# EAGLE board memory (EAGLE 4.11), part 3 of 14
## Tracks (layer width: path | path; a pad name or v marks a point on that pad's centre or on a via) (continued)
-BT00(B) (continued)
  Route3 0.254: F25.T2 191.77,19.69 187.32,19.69 187.32,20.32 130.18,77.47 130.18,86.99 128.91,88.27 E30.T2
-BT12  (via drill 0.61)
  Top 0.254: v133.35,299.72 132.08,298.45 132.08,295.91 B30.S2
  Route2 0.254: v211.46,365.12 213.36,367.03 222.88,367.03 223.52,366.4 226.06,366.4 227.33,367.67 229.87,367.67 A22.R2
  Route3 0.254: v170.18,292.1 175.26,297.18 175.26,297.81 179.07,297.81 B26.R2 | v167,358.78 163.19,354.97 163.19,342.9 158.75,338.46 158.75,311.79 149.22,302.26 149.22,296.55 v147.96,295.28
  Bottom 0.254: v211.46,365.12 210.82,365.12 209.55,363.86 205.1,363.86 204.47,363.22 201.29,363.22 200.66,363.86 198.12,363.86 197.49,363.22 188.59,363.22 187.96,363.86 183.51,363.86 182.88,364.49 A26.S2 182.25,364.49 180.97,363.22 173.99,363.22 173.35,363.86 172.09,363.86 v167,358.78 | v133.35,299.72 125.09,299.72 124.46,300.36 121.92,300.36 121.28,299.72 112.39,299.72 108.58,303.53 99.69,303.53 99.06,302.9 94.61,302.9 93.98,302.26 B33.P2 | v170.18,292.1 168.91,293.37 161.29,293.37 160.66,294 151.76,294 151.13,293.37 148.59,293.37 147.96,294 | 147.96,294 139.06,294 138.43,293.37 135.89,293.37 134.62,294.64 132.08,294.64 B30.S2 | v147.96,295.28 147.96,294
-BT13  (via drill 0.61)
  Top 0.254: v156.84,361.95 v163.83,368.94
  Route2 0.254: v142.88,362.59 145.41,360.05 149.86,360.05 150.5,360.68 155.57,360.68 v156.84,361.95 | v163.83,368.94 165.1,370.21 172.72,370.21 176.53,374.02 179.07,374.02 A26.N2
  Route3 0.254: v142.88,362.59 142.88,361.31 135.89,354.33 135.89,344.81 133.35,342.27 133.35,328.93 132.08,327.66 B30.E2
-BT(00-01)  (via drill 0.61)
  Top 0.254: v150.5,330.2 155.57,335.28 155.57,342.9 161.93,349.25 161.93,361.31 165.1,364.49 165.1,394.34 181.61,410.85 184.15,410.85 184.15,400.69 179.71,396.24 179.71,394.34 A26.F2
  Route2 0.254: v150.5,330.2 148.59,328.3 145.41,328.3 144.78,327.66 B29.E2
-BT(00-11)  (via drill 0.61)
  Top 0.254: v128.91,344.17 128.91,341 123.83,335.92 123.83,327.66 119.38,327.66 B31.E2 | v150.5,344.17 154.31,347.98 v154.31,353.7
  Route3 0.254: v186.06,357.5 187.32,358.78 187.32,372.11 201.93,386.72 204.47,386.72 A24.J2
  Bottom 0.254: v128.91,344.17 142.88,344.17 144.15,342.9 149.22,342.9 v150.5,344.17 | v154.31,353.7 162.56,353.7 166.37,357.5 175.26,357.5 175.9,356.87 184.78,356.87 185.42,357.5 v186.06,357.5
-C  (via drill 0.61)
  Route2 0.254: v277.5,368.3 260.99,351.79 250.19,351.79 245.11,356.87 237.49,356.87 233.68,360.68 224.79,360.68 220.98,356.87 215.9,356.87 v214,354.97 | v198.75,325.75 200.03,324.49 204.47,324.49 B24.F2
  Route3 0.254: v155.57,290.2 155.57,287.66 154.31,286.39 B28.V2 | B25.V2 191.77,286.39 188.59,286.39 v186.06,288.93 190.5,293.37 190.5,299.09 193.04,301.62 190.5,304.17 190.5,318.14 192.41,320.04 192.41,321.31 190.5,323.22 v190.5,327.66 | B24.K2 207.65,314.96 206.38,316.23 206.38,321.95 205.1,323.22 B24.F2 205.1,324.49 205.1,327.03 206.38,328.3 206.38,347.35 v214,354.97
  Bottom 0.254: v155.57,290.2 162.56,290.2 163.19,290.83 172.09,290.83 172.72,290.2 175.26,290.2 175.9,290.83 184.15,290.83 v186.06,288.93 | v277.5,368.3 278.13,368.3 279.4,367.03 281.94,367.03 285.12,370.21 287.65,370.21 288.29,369.57 290.83,369.57 292.74,371.48 296.55,371.48 A17.P2 | v190.5,327.66 191.13,328.3 196.22,328.3 v198.75,325.75
-CA  (via drill 0.61)
  Top 0.254: v165.1,330.2 165.1,318.14 158.75,311.79 158.75,297.18 157.48,295.91 B28.S2 | v182.25,346.71 182.88,347.35 v182.88,351.16 | A22.D2 229.87,399.42 228.6,398.15 228.6,389.25 229.87,387.99 A22.J2
  Route3 0.254: v165.1,330.2 165.1,339.73 170.81,345.44 v170.81,346.71 | v204.47,351.79 206.38,353.7 206.38,361.31 229.87,384.81 229.87,386.72 A22.J2
  Bottom 0.254: v170.81,346.71 v182.25,346.71 | v182.88,351.16 183.51,351.79 v204.47,351.79
-CAC  (via drill 0.61)
  Top 0.254: 463.55,74.93 463.55,94.61 460.38,97.79 460.38,102.23 461.64,103.5 461.64,104.14 E04.M2 | 463.55,74.93 463.55,36.83 462.28,35.56 F04.M2 | v320.68,78.1 320.68,49.53 321.94,48.26 F15.H2 | 463.55,74.93 v461.64,74.93 | A19.M2 271.14,378.46 270.51,379.1 270.51,382.91 269.88,383.54 269.88,388.62 268.61,389.89 268.61,393.06 A19.F2 | v271.14,393.7 278.13,400.69 278.13,401.32 282.57,405.77 282.57,410.21 287.65,415.29 v298.45,415.29 | v316.23,414.02 318.77,416.56 318.77,418.47 407.67,418.47 407.67,417.2 v414.65,410.21
  Route2 0.254: v271.14,393.7 268.61,393.7 A19.F2 | v298.45,415.29 299.72,414.02 v316.23,414.02 | v414.65,410.21 445.77,379.1 454.66,379.1 455.3,379.73 460.38,379.73 461.64,378.46 A04.M2 | v462.92,219.71 462.92,220.98 466.73,224.79 466.73,240.66 462.28,240.66 C04.M2
  Route3 0.254: E04.M2 462.28,105.41 463.55,106.68 463.55,169.54 462.28,170.81 D04.M2 462.28,172.09 463.55,173.35 463.55,193.04 462.28,194.31 462.28,194.94 463.55,196.22 463.55,216.53 462.28,217.81 462.28,219.07 v462.92,219.71 | v449.58,304.17 450.85,302.9 450.85,290.2 457.2,283.85 457.2,250.82 455.93,249.56 460.38,245.11 460.38,243.2 461.64,241.94 C04.M2 | A04.M2 462.28,377.19 463.55,375.92 463.55,309.88 462.28,308.61 B04.M2
  Bottom 0.254: v320.68,78.1 349.25,78.1 350.52,76.83 353.06,76.83 353.69,77.47 366.39,77.47 368.3,79.38 403.86,79.38 406.4,76.83 412.12,76.83 412.75,76.2 430.53,76.2 431.8,74.93 v461.64,74.93 | v449.58,304.17 452.12,306.71 454.66,306.71 455.3,306.07 460.38,306.07 461.64,307.34 B04.M2
-CL  (via drill 0.61)
  Top 0.254: v319.4,65.41 319.4,72.39 315.6,76.2 v315.6,81.91 | v208.91,131.44 208.28,132.08 v208.28,134.62 | v165.1,253.36 165.1,286.39 v167,288.29
  Route2 0.254: v464.82,69.22 462.92,71.12 421.64,71.12 419.74,69.22 398.14,69.22 396.88,67.94 393.06,67.94 392.43,68.58 345.44,68.58 338.45,61.59 337.19,61.59 336.55,62.23 330.2,62.23 327.02,65.41 v319.4,65.41 | v315.6,81.91 313.06,84.45 304.17,84.45 300.36,80.64 286.38,80.64 264.8,102.23 263.52,102.23 256.54,109.22 250.19,109.22 243.84,115.57 237.49,115.57 236.85,116.2 227.97,116.2 227.33,115.57 226.69,115.57 214.63,127.63 212.72,127.63 v208.91,131.44 | v208.28,134.62 207.65,135.25 205.1,135.25 201.29,139.06 192.41,139.06 179.07,152.4 179.07,154.31 178.44,154.31 169.54,163.19 163.19,163.19 v157.48,168.91
  Route3 0.254: v157.48,168.91 155.57,170.81 155.57,190.5 154.31,191.77 155.57,193.04 155.57,203.2 154.31,204.47 154.31,217.17 155.57,218.44 155.57,243.84 v165.1,253.36
  Bottom 0.254: v464.82,69.22 476.25,69.22 476.25,53.34 475.62,52.7 473.07,52.7 471.81,51.44 F03.F2 | v167,288.29 169.54,288.29 B27.U2
-CLK  (via drill 0.61)
  Top 0.254: B09.K2 398.14,314.96 398.14,318.77 396.88,320.04 396.88,328.3 395.61,329.56 B09.D2 | v59.05,349.89 59.05,351.16 47.62,362.59 47.62,372.75 41.91,372.75 41.27,372.11 41.27,367.03 42.55,365.76 A37.S2 | v95.89,346.71 107.95,346.71 v107.95,329.56
  Route2 0.254: v107.95,329.56 109.22,328.3 109.86,328.3 110.49,328.93 113.03,328.93 113.67,328.3 122.56,328.3 123.19,328.93 130.81,328.93 137.16,335.28 144.78,335.28 148.59,331.47 156.84,331.47 160.02,328.3 160.66,328.3 164.47,332.11 173.35,332.11 173.99,331.47 176.53,331.47 177.16,332.11 186.06,332.11 186.69,331.47 189.23,331.47 189.87,332.11 198.75,332.11 199.39,331.47 201.93,331.47 202.56,332.11 211.46,332.11 212.09,331.47 214.63,331.47 215.26,332.11 224.16,332.11 224.79,331.47 227.33,331.47 227.97,332.11 236.85,332.11 237.49,331.47 246.38,331.47 250.19,335.28 259.08,335.28 262.89,331.47 265.43,331.47 266.06,332.11 274.95,332.11 275.59,331.47 278.13,331.47 278.76,332.11 287.65,332.11 288.29,331.47 290.83,331.47 291.46,332.11 300.36,332.11 300.99,331.47 303.53,331.47 304.17,332.11 313.06,332.11 313.69,331.47 322.58,331.47 326.39,335.28 335.28,335.28 339.09,331.47 347.98,331.47 351.79,335.28 360.68,335.28 364.49,331.47 367.03,331.47 367.67,332.11 376.56,332.11 377.19,331.47 379.73,331.47 380.37,332.11 389.25,332.11 390.52,330.84 394.97,330.84 B09.D2
  Route3 0.254: v107.95,329.56 107.95,316.87 111.12,313.69 111.12,299.09 115.57,299.09 B31.R2
  Bottom 0.254: v107.95,329.56 103.5,329.56 B32.D2 | v59.05,349.89 60.96,347.98 81.28,347.98 81.92,347.35 85.09,347.35 85.72,346.71 v95.89,346.71
-CLL  (via drill 0.61)
  Top 0.254: v282.57,53.34 v282.57,30.48 | v302.89,57.15 304.8,59.05 304.8,75.56 v306.07,76.83 | v177.8,277.5 177.8,307.34 180.97,310.52 180.97,318.77 182.25,320.04 B26.H2 | v252.73,81.91 252.09,81.28 252.09,69.22 250.82,67.94 250.82,39.37 v261.62,28.58
  Route2 0.254: v322.58,83.82 324.49,85.72 v325.12,85.72 | v382.27,153.03 374.01,144.78 365.76,144.78 v347.98,127
  Route3 0.254: v309.25,76.83 309.88,77.47 v309.88,82.55 | v407.67,248.92 406.4,247.65 406.4,232.41 403.23,229.23 403.23,201.29 406.4,198.12 406.4,189.23 405.13,187.96 405.13,186.69 403.23,184.78 403.23,177.8 401.95,176.53 403.23,175.26 403.23,170.81 403.86,170.18 403.86,166.37 403.23,165.73 403.23,160.66 v401.32,158.75 | v347.98,127 346.07,125.09 346.07,116.84 345.44,116.2 345.44,115.57 346.07,114.93 346.07,113.03 344.81,111.76 344.81,109.85 346.07,108.58 346.07,93.98 347.35,92.71 E13.S2 | v198.12,276.23 196.85,274.96 196.85,154.31 200.66,150.5 200.66,144.78 v201.29,144.14 | v210.82,144.14 215.9,139.06 215.9,132.08 219.07,128.91 219.07,107.31 219.71,106.68 219.71,106.04 219.07,105.41 219.07,97.16 v220.98,95.25
  Bottom 0.254: v282.57,30.48 277.5,30.48 276.86,29.84 272.42,29.84 271.78,29.21 F19.P2 271.14,29.21 269.88,30.48 263.52,30.48 v261.62,28.58 | v282.57,53.34 282.57,55.25 289.56,55.25 290.19,55.88 299.08,55.88 299.72,55.25 300.99,55.25 v302.89,57.15 | v309.25,76.83 v306.07,76.83 | v309.88,82.55 311.79,84.45 314.96,84.45 315.6,83.82 v322.58,83.82 | v325.12,85.72 327.02,87.63 334.64,87.63 335.28,86.99 338.45,86.99 342.9,91.44 347.35,91.44 E13.S2 | v407.67,248.92 410.85,248.92 410.85,253.36 C08.H2 | v401.32,158.75 399.42,156.84 392.43,156.84 389.25,153.67 382.9,153.67 v382.27,153.03 | v177.8,277.5 178.44,276.86 194.94,276.86 195.58,277.5 196.85,277.5 v198.12,276.23 | v210.82,144.14 v201.29,144.14 | v220.98,95.25 224.16,92.07 224.79,92.07 226.69,90.17 235.59,90.17 236.22,90.8 238.76,90.8 245.11,84.45 250.19,84.45 v252.73,81.91
-CLR  (via drill 0.61)
  Top 0.254: v117.47,123.19 118.75,121.92 118.75,118.11 E31.H2
  Route2 0.254: v115.57,198.12 113.03,200.66 111.12,200.66 111.12,215.26 51.44,274.96 46.35,274.96 20.95,300.36 12.7,300.36 12.7,332.11 37.47,356.87 41.27,356.87 42.55,358.14 A37.U2
  Route3 0.254: v115.57,198.12 114.3,196.85 114.3,160.02 120.65,153.67 120.65,142.24 117.47,139.06 117.47,132.72 116.2,131.44 116.2,128.91 117.47,127.63 v117.47,123.19
-CM  (via drill 0.61)
  Top 0.254: v208.91,84.45 209.55,85.09 v209.55,112.39
  Bottom 0.254: v208.91,84.45 206.38,84.45 205.1,83.18 E24.V2 | v209.55,112.39 209.55,116.84 208.28,116.84 E24.H2
-CMA
  Top 0.254: F14.M2 334.64,35.56 334.64,40.64 F14.K2
-CMB  (via drill 0.61)
  Top 0.254: v429.26,48.9 429.26,50.16 433.07,50.16 F06.F2 | v182.25,208.91 182.88,208.28 v182.88,205.1 | v292.1,208.28 v292.1,181.61 | v309.25,182.25 311.15,180.34 311.15,173.35 309.88,172.09 D16.M2
  Route2 0.254: v398.14,126.36 396.24,128.27 391.16,128.27 384.18,135.25 384.18,155.57 385.44,156.84 385.44,157.48 384.81,157.48 373.38,168.91 373.38,170.81 D11.M2 | v219.71,206.38 220.98,207.64 229.24,207.64 229.87,207.01 233.68,207.01 v234.95,208.28
  Route3 0.254: v411.48,50.16 406.4,55.25 406.4,88.27 403.23,91.44 403.23,104.14 400.05,107.31 400.05,124.46 v398.14,126.36 | v46.35,255.27 47.62,254 47.62,214 v48.9,212.72
  Bottom 0.254: D11.M2 372.75,172.09 368.94,172.09 367.67,173.35 366.39,173.35 365.12,172.09 360.68,172.09 D12.M2 360.05,171.45 356.24,171.45 354.33,169.54 351.79,169.54 350.52,170.81 347.98,170.81 D13.M2 347.35,170.81 346.07,169.54 340.36,169.54 339.09,170.81 335.28,170.81 D14.M2 334.64,170.81 333.38,169.54 327.66,169.54 326.39,170.81 322.58,170.81 D15.M2 321.94,172.09 318.13,172.09 316.87,173.35 315.6,173.35 314.96,172.72 310.51,172.72 309.88,172.09 D16.M2 | v429.26,48.9 418.46,48.9 417.83,49.53 415.29,49.53 414.65,48.9 412.75,48.9 v411.48,50.16 | v46.35,255.27 41.27,255.27 40.01,256.54 C37.F2 | v48.9,212.72 49.53,212.09 75.56,212.09 76.2,212.72 97.16,212.72 97.79,212.09 130.18,212.09 130.81,211.45 132.08,211.45 133.35,212.72 145.41,212.72 149.22,208.91 179.07,208.91 179.71,209.55 181.61,209.55 v182.25,208.91 | v182.88,205.1 183.51,205.74 187.96,205.74 189.23,207.01 211.46,207.01 212.72,205.74 219.07,205.74 v219.71,206.38 | v234.95,208.28 235.59,208.91 241.3,208.91 242.57,210.19 262.89,210.19 264.8,208.28 v292.1,208.28 | v292.1,181.61 293.37,182.88 302.26,182.88 302.89,182.25 v309.25,182.25
-CML  (via drill 0.61)
  Top 0.254: v258.44,375.92 260.35,374.02 v260.35,320.68 | v266.7,281.94 v266.7,317.5 | v299.72,281.94 300.36,281.31 300.36,271.78 301.62,270.51 v301.62,80.64 | F13.E2 347.35,54.61 346.07,55.88 346.07,80.64 344.81,81.91 E13.V2
  Bottom 0.254: v258.44,375.92 252.09,375.92 248.92,379.1 244.47,379.1 243.21,380.37 A21.L2 | v260.35,320.68 261.62,319.41 264.16,319.41 266.06,317.5 v266.7,317.5 | v266.7,281.94 267.33,281.31 290.19,281.31 290.83,281.94 v299.72,281.94 | v301.62,80.64 311.15,80.64 311.79,80.01 342.26,80.01 344.17,81.91 E13.V2
-CONS  (via drill 0.61)
  Top 0.254: v501.65,271.78 v501.65,255.91
  Route2 0.254: v46.35,309.25 57.15,320.04 57.15,331.47 57.78,331.47 71.75,345.44 90.17,345.44 98.42,353.7 149.86,353.7 v161.93,365.76 | v300.36,385.45 302.89,387.99 304.8,387.99 305.44,388.62 308.61,388.62 309.25,389.25 313.06,389.25 316.87,385.45 327.66,385.45 331.47,389.25 340.36,389.25 341,388.62 349.88,388.62 353.69,392.43 361.31,392.43 368.3,385.45 378.46,385.45 382.27,389.25 389.89,389.25 396.24,382.91 403.23,382.91 409.57,376.56 416.56,376.56 420.37,372.75 429.26,372.75 429.89,373.38 431.8,373.38 445.13,360.05 454.66,360.05 455.3,360.68 464.19,360.68 470.54,354.33 476.88,354.33 477.52,353.7 492.76,353.7 497.2,358.14 499.75,358.14 A01.U2 | v429.89,82.55 479.43,132.08 479.43,156.84 481.33,156.84 498.48,173.99 498.48,189.23 v497.2,189.23
  Route3 0.254: v46.35,309.25 46.35,307.98 44.45,306.07 44.45,230.5 43.18,229.23 C37.S2 | v161.93,365.76 165.1,368.94 165.1,375.29 179.07,389.25 v181.61,389.25 | v209.55,389.89 224.79,405.13 235.59,405.13 242.57,398.15 250.82,398.15 250.82,396.24 255.27,391.8 264.16,391.8 264.8,392.43 273.69,392.43 277.5,388.62 286.38,388.62 286.38,389.89 288.93,392.43 291.46,392.43 298.45,385.45 v300.36,385.45 | v429.89,82.55 429.89,74.29 425.45,69.85 425.45,55.88 424.18,54.61 F07.E2 | v500.38,215.9 501.65,217.17 v501.65,255.91
  Bottom 0.254: v181.61,389.25 186.06,389.25 188.59,386.72 189.23,386.72 191.77,389.25 200.66,389.25 201.29,388.62 208.28,388.62 v209.55,389.89 | v497.2,189.23 497.2,192.41 497.84,192.41 501.65,196.22 501.65,215.9 v500.38,215.9 | v501.65,271.78 501.65,277.5 498.48,280.67 498.48,309.25 501.65,312.42 501.65,322.58 500.38,322.58 479.43,343.54 479.43,344.81 490.22,344.81 499.75,354.33 499.75,358.14 A01.U2
-CP  (via drill 0.61)
  Top 0.254: v170.18,269.88 171.45,271.15 171.45,286.39 v173.35,288.29
  Route2 0.254: v46.35,254 44.45,254 44.45,226.06 43.18,224.79 40.01,224.79 C37.T2 | v137.79,250.82 147.32,260.35 148.59,260.35 150.5,258.44 151.76,258.44 154.94,261.62 161.93,261.62 v170.18,269.88 | v173.35,288.29 179.07,294 185.42,294 188.59,297.18 197.49,297.18 198.12,296.55 199.39,296.55 203.2,300.36 210.19,300.36 211.46,301.62 212.09,301.62 214,299.72 222.88,299.72 226.69,303.53 231.78,303.53 232.41,304.17 234.95,304.17 236.22,302.9 238.76,302.9 239.4,303.53 240.03,303.53 241.3,302.26 245.75,302.26 B21.P2
  Bottom 0.254: v46.35,254 48.26,252.09 57.78,252.09 58.42,252.73 60.96,252.73 64.77,248.92 72.39,248.92 76.2,252.73 86.36,252.73 90.17,248.92 99.06,248.92 102.87,252.73 111.76,252.73 112.39,252.09 121.28,252.09 121.92,252.73 124.46,252.73 125.09,252.09 133.99,252.09 134.62,252.73 135.89,252.73 v137.79,250.82
-DC  (via drill 0.61)
  Top 0.254: v226.69,348.62 223.52,345.44 v223.52,339.73
  Route2 0.254: v226.69,348.62 227.97,349.89 271.78,349.89 281.94,360.05 287.65,360.05 294,366.4 300.36,366.4 300.99,367.03 307.34,367.03 310.51,370.21 313.06,370.21 313.69,369.57 316.23,369.57 316.87,370.21 325.75,370.21 326.39,369.57 330.83,369.57 331.47,368.94 A14.R2 | v223.52,339.73 222.25,338.46 217.81,338.46 214.63,341.63 173.99,341.63 167.64,335.28 161.29,335.28 160.66,334.65 151.76,334.65 147.96,338.46 139.06,338.46 132.08,331.47 123.19,331.47 119.38,335.28 110.49,335.28 104.14,328.93 97.79,328.93 97.16,328.3 88.27,328.3 84.45,332.11 75.56,332.11 68.58,325.12 61.59,325.12 60.33,326.39 v60.33,327.03
  Route3 0.254: v62.23,297.18 60.33,299.09 v60.33,327.03
  Bottom 0.254: v62.23,297.18 66.67,297.18 67.94,295.91 B35.S2 | v60.33,327.03 55.88,327.03 B36.E2
-DCA  (via drill 0.61)
  Top 0.254: 257.18,162.56 257.18,289.56 259.08,291.47 259.08,294.64 B20.S2 | 257.18,162.56 257.18,36.83 258.44,35.56 F20.M2 | v252.09,306.07 254,304.17 v254,296.55 | 257.18,162.56 v259.08,162.56
  Route2 0.254: v259.08,162.56 263.52,167 271.78,167 275.59,163.19 278.13,163.19 278.76,163.83 287.65,163.83 288.29,163.19 292.74,163.19 293.37,162.56 D17.R2
  Bottom 0.254: v252.09,306.07 251.46,306.71 247.01,306.71 246.38,307.34 B21.M2 | v254,296.55 255.27,295.28 258.44,295.28 B20.S2
-DEPS  (via drill 0.61)
  Top 0.254: v490.86,327.66 492.12,328.93 492.12,338.46 v490.86,339.73 | v379.73,349.25 374.65,354.33 374.65,359.41 v372.75,361.31 | v205.74,276.23 207.65,278.13 207.65,288.29 B24.U2 | v267.97,347.35 261.62,341 v261.62,339.73
  Route2 0.254: v490.86,339.73 485.77,344.81 479.43,344.81 476.88,347.35 447.04,347.35 v445.13,349.25 | v34.29,295.28 39.37,290.2 43.81,290.2 52.7,281.31 107.95,281.31 117.47,271.78 121.92,271.78 127.64,277.5 176.53,277.5 177.8,276.23 194.31,276.23 195.58,274.96 204.47,274.96 v205.74,276.23 | v349.25,351.79 346.07,348.62 271.78,348.62 269.88,346.71 268.61,346.71 v267.97,347.35 | v220.34,287.02 213.36,287.02 212.09,288.29 208.28,288.29 B24.U2
  Route3 0.254: v349.25,351.79 352.43,354.97 352.43,361.31 356.87,361.31 A12.T2 | v261.62,339.73 250.82,328.93 250.82,318.14 252.09,316.87 252.09,316.23 250.82,314.96 250.82,290.83 v248.92,288.93
  Bottom 0.254: v490.86,327.66 495.94,322.58 498.48,322.58 499.75,321.31 B01.H2 | v445.13,349.25 444.5,348.62 420.37,348.62 419.74,349.25 399.42,349.25 398.14,347.98 381,347.98 v379.73,349.25 | v372.75,361.31 372.11,360.68 368.3,360.68 367.67,361.31 365.12,361.31 363.86,360.05 358.77,360.05 357.5,361.31 A12.T2 | v34.29,295.28 30.48,295.28 B38.S2 | v248.92,288.93 247.01,287.02 237.49,287.02 233.68,290.83 224.79,290.83 220.98,287.02 v220.34,287.02
-DM
  Route2 0.254: E24.S2 207.65,92.71 206.38,93.98 203.84,93.98 192.41,105.41 192.41,107.31 E25.L2
-DPA  (via drill 0.61)
  Top 0.254: v254,417.2 254,373.38 256.54,373.38 257.18,374.02 257.18,382.27 258.44,383.54 A20.K2 | v151.13,415.29 150.5,415.93 150.5,417.2 149.22,418.47 97.79,418.47 v97.79,414.66 | v67.31,414.02 63.5,410.21 63.5,389.25 64.77,387.99 A35.J2
  Route3 0.254: v57.15,295.91 57.15,351.79 63.5,358.14 63.5,385.45 64.77,386.72 A35.J2
  Bottom 0.254: 57.15,294 59.05,294 63.5,289.56 67.94,289.56 B35.U2 | 57.15,294 50.16,294 46.35,290.2 45.72,290.2 45.09,290.83 36.2,290.83 35.56,290.2 28.57,290.2 27.3,291.47 B38.T2 | v254,417.2 253.37,417.83 190.5,417.83 189.23,416.56 161.29,416.56 160.66,415.93 151.76,415.93 v151.13,415.29 | v97.79,414.66 97.16,414.02 v67.31,414.02 | v57.15,295.91 57.15,294
-EM  (via drill 0.61)
  Top 0.254: v190.5,116.84 190.5,100.96 193.68,97.79 193.68,88.27 193.04,87.63 193.04,83.82 192.41,83.18 E25.V2 | v171.45,156.84 171.45,125.73 v173.35,123.82
  Route3 0.254: v100.33,192.41 101.6,191.13 v101.6,175.26
  Bottom 0.254: 191.13,117.47 v190.5,116.84 | 191.13,117.47 194.94,117.47 E25.H2 | v100.33,192.41 99.69,192.41 99.06,191.77 96.52,191.77 95.89,192.41 87,192.41 83.19,188.59 74.3,188.59 70.48,192.41 61.59,192.41 60.96,191.77 56.52,191.77 55.88,191.13 D36.E2 | v101.6,175.26 101.6,160.02 109.22,160.02 115.57,153.67 123.19,153.67 129.54,160.02 134.62,160.02 137.79,156.84 146.69,156.84 150.5,160.66 151.76,160.66 154.94,157.48 162.56,157.48 163.19,156.84 v171.45,156.84 | v173.35,123.82 178.44,118.74 187.96,118.74 188.59,119.38 189.23,119.38 191.13,117.47
-EPA  (via drill 0.61)
  Top 0.254: v480.06,83.82 482.6,81.28 485.77,81.28 485.77,91.44 482.6,94.61 v482.6,142.24 | v73.03,144.78 v73.03,301.62 | v50.8,304.8 50.8,337.82 60.33,347.35 60.33,367.67 64.77,367.67 A35.R2
  Route2 0.254: v411.48,145.41 v414.02,142.88 | A29.U2 144.15,359.41 142.88,360.68 135.89,360.68 132.08,356.87 123.19,356.87 122.56,357.5 113.67,357.5 113.03,356.87 110.49,356.87 109.86,357.5 100.97,357.5 97.16,353.7 83.82,353.7 69.85,367.67 65.41,367.67 A35.R2
  Route3 0.254: v328.3,146.69 325.75,146.69 v325.75,147.32
  Bottom 0.254: v480.06,83.82 476.88,86.99 473.07,86.99 471.81,88.27 E03.T2 | v482.6,142.24 481.96,141.6 459.74,141.6 457.83,143.51 440.69,143.51 440.06,142.88 v414.02,142.88 | v411.48,145.41 409.57,147.32 399.42,147.32 398.78,147.95 389.89,147.95 389.25,147.32 347.98,147.32 347.35,147.95 339.09,147.95 337.82,146.69 v328.3,146.69 | v325.75,147.32 325.12,146.69 289.56,146.69 288.93,147.32 288.29,147.32 287.02,146.05 243.84,146.05 242.57,144.78 222.88,144.78 222.25,145.41 201.29,145.41 198.75,142.88 150.5,142.88 147.96,145.41 117.47,145.41 116.2,144.14 90.81,144.14 90.17,144.78 87,144.78 85.72,143.51 74.3,143.51 v73.03,144.78 | v73.03,301.62 72.39,300.99 69.85,300.99 69.22,300.36 65.41,300.36 62.23,303.53 59.69,303.53 59.05,302.9 50.16,302.9 49.53,303.53 | 49.53,303.53 46.99,303.53 46.35,302.9 45.09,302.9 41.91,306.07 35.56,306.07 34.29,307.34 30.48,307.34 B38.M2 | 49.53,303.53 v50.8,304.8
-EX  (via drill 0.61)
  Top 0.254: 135.25,358.14 137.79,360.68 142.24,360.68 144.15,362.59 144.15,364.49 A29.S2 | 135.25,358.14 v134.62,357.5 | v255.91,338.46 256.54,339.09 256.54,346.71 v255.27,347.98 | v140.34,342.9 137.79,345.44 137.79,355.6 135.25,358.14
  Route2 0.254: v81.28,354.97 80.01,354.97 59.69,334.65 52.7,334.65 52.7,330.84 B36.D2 | v318.77,332.74 313.06,338.46 312.42,338.46 309.25,335.28 300.99,335.28 300.36,334.65 291.46,334.65 290.83,335.28 288.29,335.28 287.65,334.65 278.76,334.65 278.13,335.28 275.59,335.28 274.95,334.65 266.06,334.65 262.25,338.46 v255.91,338.46 | v255.27,347.98 254.63,347.35 236.85,347.35 234.95,349.25 228.6,349.25 226.69,347.35 211.46,347.35 208.91,349.89 181.61,349.89 180.97,350.52 168.91,350.52 160.02,341.63 141.6,341.63 v140.34,342.9
  Route3 0.254: v318.77,332.74 320.68,330.84 320.68,328.93 321.94,327.66 B15.E2
  Bottom 0.254: v81.28,354.97 87,360.68 89.53,360.68 92.71,357.5 99.06,357.5 99.69,356.87 108.58,356.87 109.22,357.5 111.76,357.5 112.39,356.87 121.28,356.87 121.92,357.5 124.46,357.5 125.09,356.87 133.99,356.87 v134.62,357.5
-EXS  (via drill 0.61)
  Top 0.254: v360.05,349.25 361.31,350.52 361.31,357.5 360.68,358.14 A12.U2
  Route2 0.254: v410.85,354.97 410.85,352.43 412.75,350.52 421,350.52 424.81,346.71 476.25,346.71 494.03,328.93 498.48,328.93 499.75,327.66 B01.E2 | v55.24,276.86 46.35,276.86 32.38,290.83 31.75,290.83 31.75,302.26 27.94,306.07 27.3,306.07 27.3,310.52 B38.L2 | v182.88,285.12 185.42,287.66 187.96,287.66 188.59,287.02 197.49,287.02 201.29,290.83 203.84,290.83 204.47,291.47 B24.T2 | v360.05,349.25 358.77,347.98 306.7,347.98 301.62,342.9 299.72,342.9 298.45,344.17 297.81,343.54 246.38,343.54 245.11,342.27 227.33,342.27 v225.43,340.36
  Route3 0.254: v144.78,285.12 v135.25,275.59 | v225.43,340.36 225.43,334.65 212.72,321.95 212.72,297.81 v208.28,293.37
  Bottom 0.254: v410.85,354.97 410.21,354.33 405.13,354.33 401.95,357.5 393.06,357.5 392.43,356.87 391.16,356.87 387.35,360.68 377.19,360.68 376.56,360.05 367.67,360.05 367.03,360.68 366.39,360.68 365.12,359.41 360.68,359.41 A12.U2 | v55.24,276.86 75.56,276.86 76.83,275.59 88.27,275.59 89.53,276.86 109.22,276.86 111.12,274.96 115.57,274.96 116.84,276.23 134.62,276.23 v135.25,275.59 | v144.78,285.12 147.32,287.66 149.86,287.66 150.5,287.02 159.38,287.02 160.02,287.66 162.56,287.66 163.19,287.02 170.81,287.02 173.35,289.56 178.44,284.48 182.25,284.48 v182.88,285.12 | v208.28,293.37 207.65,292.74 205.1,292.74 B24.T2
-FM  (via drill 0.61)
  Top 0.254: v218.44,106.68 219.07,107.31 219.07,118.74 220.34,120.02 220.34,123.19 E23.E2 | 60.33,96.52 57.15,99.69 57.15,102.87 55.88,104.14 E36.M2 | 60.33,96.52 66.67,96.52 66.67,137.16 v64.77,139.06 | v193.68,79.38 193.68,86.36 194.31,86.99 194.31,90.8 194.94,91.44 E25.S2 | v62.23,79.38 60.33,81.28 60.33,96.52
  Route2 0.254: v189.23,101.6 193.68,97.16 194.94,97.16 194.94,92.71 E25.S2 | v64.77,139.06 59.05,144.78 46.35,144.78 20.32,170.81 17.78,170.81 D39.M2
  Bottom 0.254: v189.23,101.6 193.68,106.04 200.66,106.04 201.29,106.68 210.19,106.68 210.82,106.04 213.36,106.04 214,106.68 v218.44,106.68 | v193.68,79.38 88.27,79.38 87.63,80.01 86.36,80.01 85.72,79.38 v62.23,79.38
-FR  (via drill 0.61)
  Top 0.254: v71.75,340.36 71.75,353.7 73.03,354.97 73.03,389.89 65.41,397.51 65.41,399.42 A35.D2
  Route3 0.254: v78.11,338.46 79.38,337.19 79.38,322.58 80.64,321.31 B34.H2
  Bottom 0.254: v78.11,338.46 75.56,338.46 74.93,337.82 74.3,337.82 v71.75,340.36
-IAC
  Top 0.254: F14.L2 331.47,38.73 330.83,39.37 330.83,43.18 330.2,43.82 330.2,48.9 331.47,50.16 F14.F2
-IC00  (via drill 0.61)
  Top 0.254: v445.77,274.96 445.77,285.12 B05.V2
  Route3 0.254: v452.12,273.05 454.02,271.15 454.02,232.41 457.2,229.23 457.2,166.37 460.38,163.19 v460.38,128.91
  Bottom 0.254: E38.D2 27.3,126.36 28.57,125.09 35.56,125.09 39.37,128.91 48.26,128.91 48.9,128.27 57.78,128.27 58.42,128.91 60.96,128.91 61.59,128.27 70.48,128.27 71.12,128.91 73.66,128.91 77.47,125.09 86.36,125.09 90.17,128.91 99.06,128.91 99.69,128.27 108.58,128.27 109.22,128.91 111.76,128.91 112.39,128.27 121.28,128.27 125.09,132.08 127.64,132.08 130.81,128.91 137.16,128.91 137.79,128.27 146.69,128.27 147.32,128.91 149.86,128.91 153.67,125.09 162.56,125.09 166.37,128.91 175.26,128.91 175.9,128.27 184.78,128.27 185.42,128.91 187.96,128.91 188.59,128.27 197.49,128.27 198.12,128.91 200.66,128.91 201.29,128.27 210.19,128.27 210.82,128.91 213.36,128.91 214,128.27 222.88,128.27 223.52,128.91 226.06,128.91 226.69,128.27 235.59,128.27 236.22,128.91 238.76,128.91 239.4,128.27 248.28,128.27 248.92,128.91 251.46,128.91 252.09,128.27 260.99,128.27 261.62,128.91 264.16,128.91 264.8,128.27 273.69,128.27 274.32,128.91 276.86,128.91 277.5,128.27 286.38,128.27 287.02,128.91 289.56,128.91 290.19,128.27 299.08,128.27 299.72,128.91 302.26,128.91 302.89,128.27 311.79,128.27 312.42,128.91 314.96,128.91 315.6,128.27 324.49,128.27 325.12,128.91 327.66,128.91 328.3,128.27 337.19,128.27 337.82,128.91 340.36,128.91 341,128.27 349.88,128.27 350.52,128.91 353.06,128.91 353.69,128.27 362.58,128.27 363.22,128.91 365.76,128.91 366.39,128.27 375.29,128.27 375.92,128.91 378.46,128.91 379.1,128.27 387.99,128.27 388.62,128.91 391.16,128.91 394.97,125.09 403.86,125.09 407.67,128.91 416.56,128.91 417.19,128.27 426.08,128.27 426.72,128.91 429.26,128.91 429.89,128.27 438.79,128.27 439.42,128.91 441.96,128.91 445.77,125.09 452.75,125.09 456.56,128.91 v460.38,128.91 466.09,128.91 468,127 471.17,127 E03.D2
  Bottom 0.254: v445.77,274.96 446.4,274.32 450.85,274.32 v452.12,273.05
-IC01  (via drill 0.61)
  Top 0.254: v465.45,170.18 463.55,172.09 463.55,186.69 460.38,189.86 v460.38,195.58 | v76.83,140.34 76.2,140.97 76.2,151.13 v78.11,153.03 | v368.3,279.4 368.94,278.77 v368.94,273.69
  Route2 0.254: v113.03,175.89 123.19,186.06 125.09,186.06 130.81,191.77 135.89,191.77 v147.32,203.2 | v151.13,231.78 153.03,233.68 158.12,233.68 158.75,234.31 158.75,238.76 160.02,240.03 162.56,240.03 163.19,239.39 172.09,239.39 175.9,243.2 184.78,243.2 185.42,242.57 187.96,242.57 191.77,246.38 200.66,246.38 201.29,245.75 210.19,245.75 210.82,246.38 213.36,246.38 214.63,245.11 215.9,245.11 217.17,246.38 226.06,246.38 226.69,245.75 235.59,245.75 236.22,246.38 238.76,246.38 239.4,245.75 246.38,245.75 v258.44,257.81 | v368.94,273.69 370.2,273.69 372.11,271.78 378.46,271.78 382.27,267.97 391.16,267.97 398.78,275.59 417.19,275.59 443.87,248.92 451.49,248.92 v452.75,247.65
  Route3 0.254: v465.45,170.18 469.9,165.73 469.9,122.55 471.17,121.28 E03.F2 | v460.38,195.58 460.38,232.41 458.47,234.31 458.47,236.22 457.2,237.49 457.2,244.47 v455.93,245.75 | v452.75,247.65 450.85,249.56 450.85,287.02 449.58,288.29 B05.U2 | v30.48,128.27 30.48,124.46 E38.E2 | v147.32,203.2 146.69,203.84 146.69,215.9 149.22,218.44 149.22,229.87 v151.13,231.78 | v309.25,263.53 319.4,273.69 v319.4,282.58
  Bottom 0.254: v455.93,245.75 454.66,245.75 v452.75,247.65 | v30.48,128.27 37.47,135.25 45.72,135.25 50.8,140.34 v76.83,140.34 | v78.11,153.03 101.6,176.53 111.76,176.53 112.39,175.89 v113.03,175.89 | v258.44,257.81 257.18,259.08 257.18,261.62 264.16,261.62 264.8,262.25 273.69,262.25 274.32,261.62 276.86,261.62 277.5,262.25 286.38,262.25 287.02,261.62 289.56,261.62 290.19,262.25 294.64,262.25 295.27,261.62 302.26,261.62 302.89,262.25 307.98,262.25 v309.25,263.53 | v319.4,282.58 341,282.58 341.63,281.94 353.06,281.94 355.6,279.4 v368.3,279.4
-IC02  (via drill 0.61)
  Top 0.254: v59.69,28.58 83.82,4.44 113.67,4.44 113.67,0.63 194.31,0.63 v194.31,4.44 | v255.91,5.08 256.54,4.44 256.54,3.17 257.18,2.54 279.4,2.54 v279.4,13.34 | v292.1,15.24 292.1,12.06 302.26,1.9 325.75,1.9 325.75,10.79 327.02,12.06 327.02,29.21 328.93,31.12 v328.93,31.75
  Route2 0.254: v194.31,4.44 194.94,3.81 221.62,3.81 223.52,5.71 231.78,5.71 233.68,3.81 254.63,3.81 v255.91,5.08 | v332.11,34.29 334.01,36.2 340.36,36.2 341,36.83 349.88,36.83 350.52,36.2 353.06,36.2 353.69,36.83 362.58,36.83 363.22,36.2 365.76,36.2 369.57,40.01 370.2,40.01 371.48,41.27 371.48,45.72 375.29,45.72 382.27,52.7 386.71,52.7 393.06,59.05 403.86,59.05 404.5,58.42 413.38,58.42 420.37,65.41 429.26,65.41 429.89,64.77 438.79,64.77 442.6,68.58 464.19,68.58 464.82,67.94 469.9,73.02 469.9,113.66 471.17,113.66 E03.J2
  Route3 0.254: v33.66,47.62 31.75,49.53 31.75,115.57 30.48,116.84 E38.H2 | v449.58,207.64 449.58,214 447.68,215.9 447.68,226.06 444.5,229.23 444.5,238.76 447.68,241.94 447.68,290.2 446.4,291.47 B05.T2 | v490.86,207.64 492.12,206.38 492.12,142.88 490.86,141.6 490.86,135.25 492.12,133.99 492.12,126.36 v490.86,125.09
  Bottom 0.254: v33.66,47.62 45.09,36.2 48.26,36.2 48.9,36.83 51.44,36.83 v59.69,28.58 | v279.4,13.34 280.67,14.61 289.56,14.61 290.19,13.97 290.83,13.97 v292.1,15.24 | v328.93,31.75 331.47,34.29 v332.11,34.29 | v490.86,207.64 v449.58,207.64 | v490.86,125.09 485.14,119.38 478.79,119.38 474.35,114.93 471.81,114.93 E03.J2
-IC03  (via drill 0.61)
  Top 0.254: v68.58,214 66.67,215.9 v66.67,298.45 | v491.49,208.91 492.12,209.55 492.12,219.07 493.39,220.34 492.12,221.61 492.12,238.76 v490.86,240.03
  Route2 0.254: v17.78,126.36 23.5,132.08 32.38,132.08 36.2,128.27 45.09,128.27 52.07,135.25 60.96,135.25 61.59,134.62 62.23,134.62 71.75,144.14 71.75,147.32 74.3,147.32 76.2,149.22 76.2,163.19 v74.3,163.19 | v161.93,410.21 168.28,416.56 192.41,416.56 195.58,419.74 266.06,419.74 266.7,419.1 424.18,419.1 425.45,420.37 447.04,420.37 451.49,415.93 457.83,415.93 504.82,368.94 504.82,313.06 496.57,313.06 v490.86,307.34 | v458.47,254.63 450.85,262.25 450.85,294.64 449.58,294.64 B05.S2
  Route3 0.254: v74.3,163.19 73.03,164.47 73.03,209.55 v68.58,214 | v93.98,293.37 104.78,304.17 104.78,340.36 130.18,365.76 130.18,372.75 161.93,404.5 v161.93,410.21 | v496.57,137.16 495.3,138.43 495.3,205.1 v491.49,208.91
  Bottom 0.254: v17.78,126.36 16.51,125.09 15.88,125.09 15.88,116.84 20.32,112.39 20.95,112.39 21.59,113.03 28.57,113.03 29.84,111.76 E38.K2 | v66.67,298.45 68.58,296.55 73.66,296.55 74.3,297.18 75.56,297.18 78.74,294 81.92,294 82.55,294.64 85.72,294.64 87,293.37 v93.98,293.37 | v490.86,307.34 488.95,305.44 488.95,297.18 478.79,297.18 472.44,290.83 466.09,290.83 465.45,290.2 456.56,290.2 452.12,294.64 449.58,294.64 B05.S2 | v496.57,137.16 495.3,137.16 495.3,116.84 494.03,115.57 493.39,115.57 492.76,116.2 482.6,116.2 476.25,109.85 473.07,109.85 471.81,108.58 E03.L2 | v490.86,240.03 485.14,245.75 478.79,245.75 474.98,249.56 468.63,249.56 465.45,252.73 460.38,252.73 v458.47,254.63
-IC04  (via drill 0.61)
  Top 0.254: v20.32,184.15 22.23,186.06 22.23,233.68 v20.95,234.95 | v211.46,410.21 212.72,410.21 215.26,412.75 249.56,412.75 v249.56,410.21 | v444.5,305.44 444.5,302.26 445.77,300.99 445.77,299.09 B05.R2
  Route2 0.254: v20.32,184.15 12.06,175.89 9.53,175.89 9.53,116.84 16.51,109.85 20.95,109.85 21.59,109.22 29.84,109.22 29.84,105.41 E38.M2 | v93.98,331.47 110.49,347.98 158.75,347.98 v159.38,348.62 | v502.92,130.18 476.25,103.5 473.07,103.5 471.81,102.23 E03.N2 | v499.75,262.89 485.14,277.5 472.44,277.5 466.09,283.85 462.92,283.85 448.94,297.81 446.4,297.81 B05.R2
  Route3 0.254: v20.95,234.95 19.05,236.85 v19.05,310.52 | v159.38,348.62 162.56,351.79 162.56,355.6 174.62,367.67 174.62,378.46 191.77,395.61 200.03,395.61 200.03,398.78 v211.46,410.21 | v249.56,410.21 260.99,421.64 309.88,421.64 309.88,421 311.15,419.74 409.57,419.74 409.57,407.04 434.98,381.64 434.98,351.16 444.5,341.63 v444.5,305.44 | v502.92,130.18 504.82,132.08 504.82,257.81 v499.75,262.89
  Bottom 0.254: v19.05,310.52 19.05,321.95 22.86,321.95 29.21,328.3 35.56,328.3 36.2,328.93 42.55,328.93 45.72,332.11 48.26,332.11 48.9,331.47 57.78,331.47 58.42,332.11 60.96,332.11 61.59,331.47 70.48,331.47 71.12,332.11 73.66,332.11 74.3,331.47 83.19,331.47 83.82,332.11 86.36,332.11 87,331.47 v93.98,331.47
-IC05  (via drill 0.61)
  Top 0.254: v28.57,120.65 28.57,100.33 29.84,99.06 E38.P2 | v226.69,142.24 227.97,143.51 227.97,151.13 228.6,151.76 v228.6,215.9 | v414.02,213.36 415.93,215.26 v415.93,238.12 | v439.42,240.03 441.32,241.94 441.32,269.24 444.5,272.42 v444.5,300.99 | v468.63,349.89 468.63,354.97 472.44,358.78 472.44,360.68 471.81,361.31 A03.T2 | v447.68,349.25 447.68,303.53 448.94,302.26 B05.P2
  Route3 0.254: v26.04,121.92 25.4,122.55 v25.4,142.24
  Bottom 0.254: v28.57,120.65 28.57,121.92 v26.04,121.92 | v25.4,142.24 26.04,142.88 60.96,142.88 61.59,142.24 100.97,142.24 102.23,143.51 104.14,143.51 104.78,142.88 117.47,142.88 118.75,144.14 140.97,144.14 141.6,144.78 146.05,144.78 149.22,141.6 226.06,141.6 v226.69,142.24 | v228.6,215.9 229.24,215.26 316.23,215.26 316.87,215.9 330.2,215.9 331.47,214.63 347.98,214.63 349.25,213.36 379.73,213.36 380.37,214 387.99,214 389.89,212.09 411.48,212.09 412.75,213.36 v414.02,213.36 | v415.93,238.12 417.19,239.39 426.08,239.39 426.72,240.03 429.26,240.03 429.89,239.39 438.79,239.39 v439.42,240.03 | v444.5,300.99 448.94,300.99 B05.P2 | v468.63,349.89 468,349.25 v447.68,349.25
-IC06  (via drill 0.61)
  Top 0.254: v200.03,142.88 v200.03,210.19 | v229.87,208.28 v229.87,216.53 | v447.68,214.63 447.68,239.39 444.5,242.57 444.5,271.15 447.04,273.69 447.04,284.48 447.68,285.12 447.68,302.26 446.4,303.53 446.4,304.17 B05.N2 445.77,305.44 444.5,306.71 444.5,347.35 v445.13,347.98
  Route2 0.254: v147.96,144.14 118.11,144.14 95.89,121.92 87,121.92 86.36,122.55 77.47,122.55 67.94,113.03 61.59,113.03 60.96,112.39 53.34,112.39 34.29,93.34 31.11,93.34 30.48,92.71 E38.S2
  Route3 0.254: v469.9,349.89 469.9,366.4 471.17,367.67 A03.R2
  Bottom 0.254: v147.96,144.14 149.86,142.24 199.39,142.24 v200.03,142.88 | v200.03,210.19 222.25,210.19 224.16,208.28 v229.87,208.28 | v229.87,216.53 230.5,215.9 315.6,215.9 316.23,216.53 330.83,216.53 332.11,215.26 348.62,215.26 349.88,214 379.1,214 379.73,214.63 388.62,214.63 390.52,212.72 410.85,212.72 412.75,214.63 v447.68,214.63 | v469.9,349.89 468,347.98 v445.13,347.98
-IC07  (via drill 0.61)
  Top 0.254: v83.82,80.64 85.72,80.64 v85.72,144.78 | v218.44,147.95 219.07,148.59 v219.07,200.66 | v236.22,202.56 236.85,203.2 v236.85,217.17 | v469.26,215.9 469.9,216.53 v469.9,285.12 | v454.02,358.78 454.02,349.89 452.12,347.98 452.12,338.46 450.85,337.19 450.85,315.6 v452.12,314.33
  Route2 0.254: v469.9,285.12 449.58,305.44 449.58,307.34 B05.M2
  Route3 0.254: v454.02,358.78 454.02,359.41 457.2,362.59 457.2,382.91 465.45,382.91 466.73,381.64 466.73,375.29 471.17,375.29 A03.N2 | v452.12,314.33 449.58,311.79 449.58,308.61 B05.M2
  Bottom 0.254: v83.82,80.64 39.37,80.64 35.56,84.45 27.3,84.45 27.3,88.27 E38.T2 | v85.72,144.78 86.36,145.41 114.94,145.41 115.57,144.78 117.47,146.69 150.5,146.69 153.67,143.51 198.12,143.51 200.66,146.05 216.53,146.05 v218.44,147.95 | v219.07,200.66 220.34,201.93 226.06,201.93 226.69,201.29 234.95,201.29 v236.22,202.56 | v236.85,217.17 237.49,216.53 314.96,216.53 315.6,217.17 327.02,217.17 330.2,220.34 332.74,220.34 333.38,219.71 333.38,216.53 349.88,216.53 351.15,215.26 377.82,215.26 378.46,215.9 399.42,215.9 400.05,216.53 424.81,216.53 425.45,215.9 v469.26,215.9
-IC08  (via drill 0.61)
  Top 0.254: v182.88,78.1 184.15,79.38 184.15,208.28 181.61,210.82 v181.61,220.34 | v223.52,223.52 222.25,224.79 v222.25,270.51 | v303.53,276.23 v303.53,285.75 | v343.54,287.02 346.07,287.02 v346.07,292.1 | v445.77,307.98 445.77,310.52 B05.L2
  Route2 0.254: v181.61,220.34 182.25,220.98 187.96,220.98 188.59,220.34 197.49,220.34 201.29,224.16 205.74,224.16 208.91,227.33 213.36,227.33 217.17,223.52 v223.52,223.52 | v464.82,320.68 462.92,318.77 457.83,318.77 450.85,311.79 446.4,311.79 B05.L2
  Route3 0.254: v236.22,271.78 v236.22,276.86 | v464.82,320.68 466.73,322.58 466.73,345.44 473.07,351.79 473.07,379.1 471.81,380.37 A03.L2
  Bottom 0.254: v182.88,78.1 175.9,78.1 173.99,76.2 160.02,76.2 158.75,77.47 31.75,77.47 27.3,81.91 E38.V2 | v222.25,270.51 223.52,271.78 226.06,271.78 226.69,271.15 235.59,271.15 v236.22,271.78 | v236.22,276.86 236.85,277.5 270.51,277.5 271.78,276.23 v303.53,276.23 | v303.53,285.75 305.44,287.66 314.96,287.66 315.6,287.02 324.49,287.02 325.12,287.66 327.66,287.66 328.3,287.02 337.19,287.02 337.82,287.66 340.36,287.66 341,287.02 v343.54,287.02 | v346.07,292.1 347.98,294 353.06,294 353.69,293.37 362.58,293.37 363.22,294 365.76,294 366.39,293.37 375.29,293.37 375.92,294 378.46,294 379.1,293.37 387.99,293.37 391.8,297.18 400.69,297.18 404.5,293.37 411.48,293.37 421,302.9 429.26,302.9 433.07,306.71 441.96,306.71 442.6,306.07 443.87,306.07 v445.77,307.98
-IC09  (via drill 0.61)
  Top 0.254: v83.82,144.78 85.72,146.69 85.72,269.24 92.08,275.59 92.08,342.27 88.9,345.44 88.9,398.15 85.72,401.32 85.72,412.75 v93.34,420.37 | v468.63,417.83 469.9,416.56 469.9,389.25 471.17,387.99 A03.J2 | v427.36,315.6 425.45,315.6 425.45,383.54 428.62,386.72 v428.62,417.83
  Route2 0.254: v57.15,121.28 74.93,139.06 78.11,139.06 v83.82,144.78
  Bottom 0.254: v57.15,121.28 54.61,121.28 53.98,121.92 48.9,121.92 48.26,122.55 45.72,122.55 45.09,121.92 40.01,121.92 40.01,126.36 E37.D2 | v93.34,420.37 93.98,421 153.67,421 156.84,417.83 158.75,417.83 159.38,418.47 187.32,418.47 188.59,419.74 264.8,419.74 266.06,418.47 267.33,418.47 269.24,420.37 307.98,420.37 309.88,418.47 323.85,418.47 325.12,419.74 414.02,419.74 415.93,417.83 v428.62,417.83 v468.63,417.83 | v427.36,315.6 427.99,316.23 430.53,316.23 431.17,315.6 440.06,315.6 440.69,316.23 447.68,316.23 448.94,314.96 B05.K2
-IC10  (via drill 0.61)
  Top 0.254: v71.12,125.09 73.03,125.09 v73.03,143.51 | v90.17,143.51 92.08,145.41 v92.08,273.05 | v96.52,274.32 98.42,276.23 98.42,334.01 v103.5,339.09 | v144.15,344.17 144.78,344.81 144.78,356.87 149.22,361.31 v149.22,417.2 | v471.17,414.02 473.07,412.12 473.07,395.61 471.81,394.34 A03.F2 | v435.61,319.41 434.98,320.04 434.98,329.56 438.15,332.74 438.15,383.54 441.32,386.72 v441.32,416.56
  Route2 0.254: v103.5,339.09 106.05,341.63 136.53,341.63 139.06,344.17 v144.15,344.17
  Bottom 0.254: v71.12,125.09 70.48,125.73 61.59,125.73 60.96,125.09 58.42,125.09 57.78,125.73 48.9,125.73 47.62,124.46 43.18,124.46 E37.E2 | v73.03,143.51 73.66,142.88 89.53,142.88 v90.17,143.51 | v92.08,273.05 92.08,274.32 v96.52,274.32 | v149.22,417.2 159.38,417.2 160.02,417.83 187.96,417.83 189.23,419.1 264.16,419.1 265.43,417.83 268.61,417.83 270.51,419.74 307.34,419.74 309.25,417.83 324.49,417.83 325.75,419.1 413.38,419.1 415.93,416.56 v441.32,416.56 468.63,416.56 v471.17,414.02 | v435.61,319.41 440.06,319.41 440.69,318.77 445.13,318.77 445.77,318.14 B05.J2
-IC11  (via drill 0.61)
  Top 0.254: v87,120.65 88.9,122.55 v88.9,251.46 | v96.52,252.73 98.42,254.63 98.42,274.96 100.97,277.5 100.97,287.66 101.6,288.29 v101.6,332.74 | v115.57,339.73 123.83,347.98 123.83,399.42 v133.99,409.58 | v464.82,414.02 466.73,412.12 v466.73,400.05
  Route2 0.254: v101.6,332.74 107.31,338.46 111.76,338.46 112.39,337.82 113.67,337.82 v115.57,339.73
  Route3 0.254: v466.73,400.05 466.73,398.15 458.47,398.15 454.66,401.96 445.77,401.96 434.98,391.16 434.98,389.89 444.5,380.37 444.5,351.16 447.68,347.98 447.68,322.58 448.94,321.31 B05.H2
  Bottom 0.254: v87,120.65 81.92,115.57 74.3,115.57 70.48,119.38 61.59,119.38 60.96,118.74 58.42,118.74 57.78,119.38 48.9,119.38 48.26,118.74 43.81,118.74 43.18,118.11 E37.H2 | v88.9,251.46 90.17,252.73 v96.52,252.73 | v133.99,409.58 137.79,413.39 146.69,413.39 149.86,416.56 160.02,416.56 160.66,417.2 188.59,417.2 189.87,418.47 263.52,418.47 264.8,417.2 269.24,417.2 271.14,419.1 306.7,419.1 308.61,417.2 325.12,417.2 326.39,418.47 412.75,418.47 415.29,415.93 440.69,415.93 442.6,414.02 v464.82,414.02 | v466.73,400.05 471.17,400.05 A03.D2
-INH1  (via drill 0.61)
  Top 0.254: D27.M2 170.18,172.09 171.45,173.35 171.45,182.25 172.72,183.51 172.72,185.42 171.45,186.69 171.45,193.04 168.28,196.22 168.28,217.17 167,218.44 C27.V2 | v231.78,223.52 230.5,222.25 230.5,219.71 C22.V2
  Bottom 0.254: 190.5,217.17 191.77,218.44 C25.V2 | 190.5,217.17 172.09,217.17 170.81,218.44 167,218.44 C27.V2 | 190.5,217.17 228.6,217.17 229.87,218.44 C22.V2 | v231.78,223.52 236.85,223.52 238.76,225.42 242.57,225.42 C21.T2
-INHIBIT  (via drill 0.61)
  Top 0.254: v83.82,201.93 84.45,202.56 v84.45,217.17 | v309.88,297.81 309.88,295.91 B16.S2
  Route2 0.254: v309.88,297.81 307.98,299.72 300.99,299.72 300.36,300.36 299.72,300.36 297.18,297.81 296.55,297.81 294.64,299.72 288.29,299.72 281.94,306.07 275.59,306.07 274.95,306.71 266.06,306.71 265.43,306.07 262.89,306.07 259.08,309.88 251.46,309.88 247.65,306.07 237.49,306.07 236.85,306.71 228.6,306.71 222.25,300.36 217.81,300.36 211.46,306.71 208.91,306.71 205.74,303.53 199.39,303.53 198.75,302.9 189.87,302.9 189.23,303.53 186.69,303.53 186.06,302.9 179.71,302.9 173.35,296.55 164.47,296.55 163.83,297.18 161.29,297.18 160.66,296.55 151.76,296.55 147.96,300.36 139.06,300.36 132.08,293.37 123.19,293.37 119.38,297.18 110.49,297.18 104.14,290.83 97.79,290.83 96.52,289.56 93.98,289.56 B33.U2
  Route3 0.254: v83.82,201.93 82.55,200.66 82.55,113.66 85.09,111.12 85.09,109.85 85.72,109.22 85.72,106.04 80.01,106.04 69.85,95.88 69.85,93.98 61.59,93.98 60.33,92.71 55.88,92.71 E36.S2 | v84.45,217.17 85.72,218.44 85.72,278.77 93.34,286.39 93.34,288.29 B33.U2
-INT_REQ  (via drill 0.61)
  Top 0.254: v48.9,95.88 50.8,93.98 50.8,48.26 55.24,43.82 55.24,41.91 F36.K2 | v42.55,147.32 38.1,142.88 v38.1,111.76
  Route2 0.254: v172.09,371.48 170.18,373.38 165.74,373.38 163.83,375.29 161.93,375.29 160.66,376.56 153.67,376.56 152.4,375.29 149.22,375.29 145.41,379.1 139.06,379.1 138.43,379.73 135.89,379.73 135.25,379.1 126.36,379.1 125.73,379.73 123.19,379.73 122.56,379.1 113.67,379.1 104.14,388.62 97.79,388.62 91.44,394.97 v86.36,394.97
  Route3 0.254: B40.N2 1.91,305.44 3.17,306.71 3.17,325.12 4.45,326.39 B40.E2 5.08,327.66 6.35,328.93 6.35,394.97 5.08,396.24 A40.E2 | v14.61,151.13 15.88,152.4 15.88,165.73 17.14,167 18.41,167 18.41,168.28 16.51,170.18 13.34,170.18 13.34,173.35 12.7,173.99 12.7,200.66 12.06,201.29 12.06,201.93 12.7,202.56 12.7,237.49 9.53,240.66 9.53,276.23 v6.35,279.4
  Bottom 0.254: v48.9,95.88 43.81,100.96 43.18,100.96 43.18,104.14 E37.M2 43.18,105.41 43.81,105.41 43.81,106.04 v38.1,111.76 | D36.V2 52.07,148.59 47.62,148.59 46.35,147.32 v42.55,147.32 41.91,146.69 19.05,146.69 v14.61,151.13 | v172.09,371.48 173.99,371.48 175.9,369.57 176.53,369.57 177.16,370.21 186.06,370.21 186.69,369.57 189.23,369.57 189.87,370.21 198.75,370.21 199.39,369.57 203.84,369.57 204.47,368.94 A24.R2 | v86.36,394.97 85.72,395.61 81.92,395.61 78.74,392.43 74.3,392.43 67.94,386.08 63.5,386.08 62.23,387.35 60.96,387.35 55.88,392.43 46.99,392.43 46.35,391.8 37.47,391.8 30.48,398.78 21.59,398.78 17.78,394.97 8.89,394.97 7.62,396.24 5.08,396.24 A40.E2 | v6.35,279.4 6.35,283.85 3.17,287.02 3.17,304.17 1.91,304.17 B40.N2
-IO_SKP  (via drill 0.61)
  Top 0.254: B40.P2 4.45,302.26 4.45,307.34 B40.M2 | v395.61,384.81 393.7,386.72 393.7,415.29 391.16,417.83 319.4,417.83 319.4,413.39 v318.13,412.12 | v143.51,410.85 140.34,414.02 103.5,414.02 103.5,410.85 v95.89,403.23 | v49.53,113.03 50.8,114.3 50.8,149.86 v52.7,151.76 | v417.19,5.08 419.1,6.98 419.1,26.03 419.74,26.67 419.74,30.48 420.37,31.12 F07.N2 | v144.78,4.44 142.24,6.98 117.47,6.98 117.47,13.34 116.84,13.97 110.49,13.97 109.86,14.61 100.97,14.61 97.16,10.79 79.38,10.79 79.38,26.03 73.03,32.38 73.03,78.74 v69.85,81.91 | v62.87,209.55 63.5,208.91 63.5,167 64.77,165.73 v64.77,164.47
  Route2 0.254: v395.61,384.81 398.14,384.81 A09.K2 | v281.31,408.31 278.13,411.48 v248.28,411.48 | v198.12,410.21 196.22,412.12 169.54,412.12 161.93,404.5 151.76,404.5 145.41,410.85 v143.51,410.85 | v4.45,373.38 3.17,372.11 3.17,308.61 4.45,308.61 B40.M2 | v417.19,5.08 412.75,0.63 379.73,0.63 377.82,2.54 377.19,2.54 375.29,0.63 287.65,0.63 285.75,2.54 264.8,2.54 260.99,6.35 260.35,6.35 256.54,2.54 222.88,2.54 222.25,3.17 146.05,3.17 v144.78,4.44 | v11.43,299.09 35.56,274.96 36.83,274.96 53.98,257.81 53.98,209.55 v62.87,209.55
  Route3 0.254: v318.13,412.12 309.25,412.12 309.25,412.75 307.34,414.66 304.17,414.66 304.17,415.29 302.89,416.56 296.55,416.56 296.55,413.39 290.83,407.67 288.29,407.67 287.65,408.31 v281.31,408.31
  Bottom 0.254: v248.28,411.48 247.65,412.12 201.29,412.12 199.39,410.21 v198.12,410.21 | v95.89,403.23 78.74,386.08 72.39,386.08 71.75,385.45 62.87,385.45 62.23,386.08 59.69,386.08 55.88,382.27 46.99,382.27 43.18,386.08 34.29,386.08 30.48,382.27 21.59,382.27 20.95,382.91 12.06,382.91 8.26,379.1 3.81,379.1 3.17,378.46 3.17,373.38 v4.45,373.38 | 47.62,112.39 48.26,112.39 48.9,113.03 v49.53,113.03 | 47.62,112.39 43.81,112.39 43.18,111.76 E37.K2 | D36.U2 55.24,151.76 v52.7,151.76 50.8,151.76 50.8,156.21 51.44,156.84 57.15,156.84 v64.77,164.47 | v69.85,81.91 47.62,104.14 47.62,112.39 | v11.43,299.09 10.16,300.36 5.71,300.36 5.08,300.99 B40.P2
-IO_SKS  (via drill 0.61)
  Route2 0.254: v476.88,327.03 457.83,346.08 424.18,346.08 420.37,349.89 411.48,349.89 387.99,373.38 381,373.38 380.37,374.02 377.82,374.02 375.92,372.11 373.38,372.11 A11.P2
  Route3 0.254: v502.92,202.56 501.65,201.29 501.65,189.86 500.38,188.59 500.38,186.06 501.65,184.78 501.65,135.89 498.48,132.72 498.48,129.54 504.82,123.19 504.82,61.59 476.25,33.02 476.25,26.03 471.81,26.03 F03.R2 | v483.87,280.67 482.6,281.94 482.6,321.31 v476.88,327.03
  Bottom 0.254: A11.P2 372.75,372.11 370.84,374.02 370.2,374.02 A11.N2 | v502.92,202.56 502.92,217.17 501.65,218.44 501.65,252.73 497.2,252.73 495.3,254.63 495.3,271.78 496.57,273.05 496.57,280.67 v483.87,280.67
-IOP1  (via drill 0.61)
  Top 0.254: A40.U2 4.45,359.41 4.45,364.49 A40.S2 | v7.62,366.4 6.35,367.67 6.35,382.27 5.08,383.54 A40.K2 | v24.77,119.38 24.77,121.92 25.4,122.55 25.4,127.63 28.57,130.81 28.57,150.5 29.84,151.76 D38.U2
  Route3 0.254: v24.77,119.38 28.57,115.57 28.57,51.44 38.1,41.91 42.55,41.91 F37.K2 | v10.79,342.9 12.7,341 12.7,241.94 v15.88,238.76 | v23.5,219.71 22.23,218.44 22.23,183.51 25.4,180.34 25.4,159.38 29.84,154.94 29.84,153.03 D38.U2
  Bottom 0.254: v7.62,366.4 6.99,365.76 5.08,365.76 A40.S2 | F37.K2 43.18,40.64 43.81,40.01 48.26,40.01 49.53,38.73 52.07,38.73 F36.L2 | v10.79,342.9 5.08,342.9 5.08,358.14 A40.U2 | v15.88,238.76 15.88,227.33 v23.5,219.71
-IOP2  (via drill 0.61)
  Top 0.254: D38.N2 27.3,168.91 27.94,169.54 27.94,173.35 28.57,173.99 28.57,191.77 27.3,193.04 D38.D2 | v31.75,164.47 31.75,43.18 30.48,41.91 F38.K2 | v81.28,373.38 85.72,368.94 85.72,354.97 82.55,351.79 82.55,320.04 81.92,319.41 81.92,315.6 81.28,314.96 B34.K2 | v326.39,415.93 349.88,415.93 365.12,400.69 369.57,400.69 A11.D2 | v137.79,412.12 114.3,412.12 114.3,401.32 106.68,393.7 v106.68,393.06 | v76.2,211.45 76.2,226.06 81.28,231.14 v81.28,233.04
  Route3 0.254: 410.85,368.3 410.85,370.84 A08.P2 | v410.85,367.03 410.85,368.3 | 410.85,368.3 383.54,395.61 383.54,396.24 378.46,401.32 378.46,401.96 375.92,401.96 374.65,400.69 370.2,400.69 A11.D2 | v326.39,415.93 323.85,415.93 322.58,414.66 v318.13,414.66 | v26.04,209.55 26.67,208.91 26.67,206.38 25.4,205.1 25.4,195.58 26.67,194.31 D38.D2 | v81.28,233.04 82.55,234.31 82.55,288.29 85.72,291.47 85.72,307.34 81.28,311.79 81.28,313.69 B34.K2
  Bottom 0.254: v31.75,164.47 31.75,167.64 27.3,167.64 D38.N2 | v410.85,367.03 408.31,367.03 408.31,362.59 A08.T2 | 80.64,374.02 78.74,375.92 72.39,375.92 71.75,376.56 62.87,376.56 62.23,375.92 59.69,375.92 55.88,379.73 46.99,379.73 43.18,375.92 34.29,375.92 30.48,379.73 21.59,379.73 20.95,379.1 12.06,379.1 11.43,379.73 10.16,379.73 8.89,378.46 5.08,378.46 A40.M2 | 80.64,374.02 v81.28,373.38 | v318.13,414.66 317.5,415.29 306.7,415.29 304.17,412.75 294,412.75 293.37,413.39 269.24,413.39 268.61,414.02 252.09,414.02 250.82,415.29 196.22,415.29 194.94,414.02 191.13,414.02 190.5,414.66 163.19,414.66 162.56,414.02 156.21,414.02 154.94,412.75 148.59,412.75 147.96,412.12 v137.79,412.12 | v106.68,393.06 93.34,379.73 86.36,379.73 80.64,374.02 | v26.04,209.55 26.04,211.45 v76.2,211.45
-IOP4  (via drill 0.61)
  Top 0.254: 19.05,140.34 19.05,234.31 22.23,237.49 v22.23,277.5 | 19.05,140.34 19.05,43.18 17.78,41.91 F39.K2 | v45.72,279.4 50.8,284.48 50.8,290.2 52.07,291.47 B36.T2 52.07,292.74 52.07,294.64 47.62,299.09 47.62,325.75 | 47.62,325.75 v46.35,327.03 | v161.93,347.35 162.56,347.98 162.56,351.16 165.1,353.7 165.1,360.05 166.37,361.31 A27.T2 | v55.88,345.44 47.62,345.44 47.62,325.75 | v401.95,104.14 400.05,106.04 400.05,139.06 398.78,140.34 v398.78,146.69 | v19.68,140.34 19.05,140.34 | v28.57,346.08 28.57,382.27 29.84,383.54 A38.K2
  Route2 0.254: v46.35,327.03 43.18,327.03 B37.E2
  Route3 0.254: v347.35,143.51 v347.35,146.69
